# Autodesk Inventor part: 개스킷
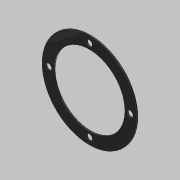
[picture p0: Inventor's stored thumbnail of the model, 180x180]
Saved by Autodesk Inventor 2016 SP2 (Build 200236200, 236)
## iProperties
Created: 2019-05
Part Number: 개스킷
Material: 고무
Document SubType Name: Modeling
Designer: mduedu
Density: 1 g/cm^3
Appearance: 고무 - 검은색 - 버전 1.1
Author: mduedu
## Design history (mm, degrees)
sketch "스케치1"
  geometry: C1 r 27 at (0, 0); C2 r 36 at (0, 0); 1 further point
  constraints: 2 centre point, 2 coincident
  dimensions: "d0" = 54 diameter of C1; "d1" = 72 diameter of C2
extrude "돌출1" new body sketch "스케치1" distance "d2" = 1; taper "d3" = 0 deg
sketch "스케치2" dims "d4" = 62
  geometry: C1 r 2.25 at (0, 31); 2 further points
  constraints: 2 vertical alignment, 1 centre point, 1 coincident, 2 other
  dimensions: "d5" = 4.5 diameter of C1
extrude "돌출2" cut sketch "스케치2" stored distance "d6" = 10; taper "d7" = 0 deg
node "솔리드1"
pattern_circular "원형 패턴1" dims angle "d9" = 360 deg
